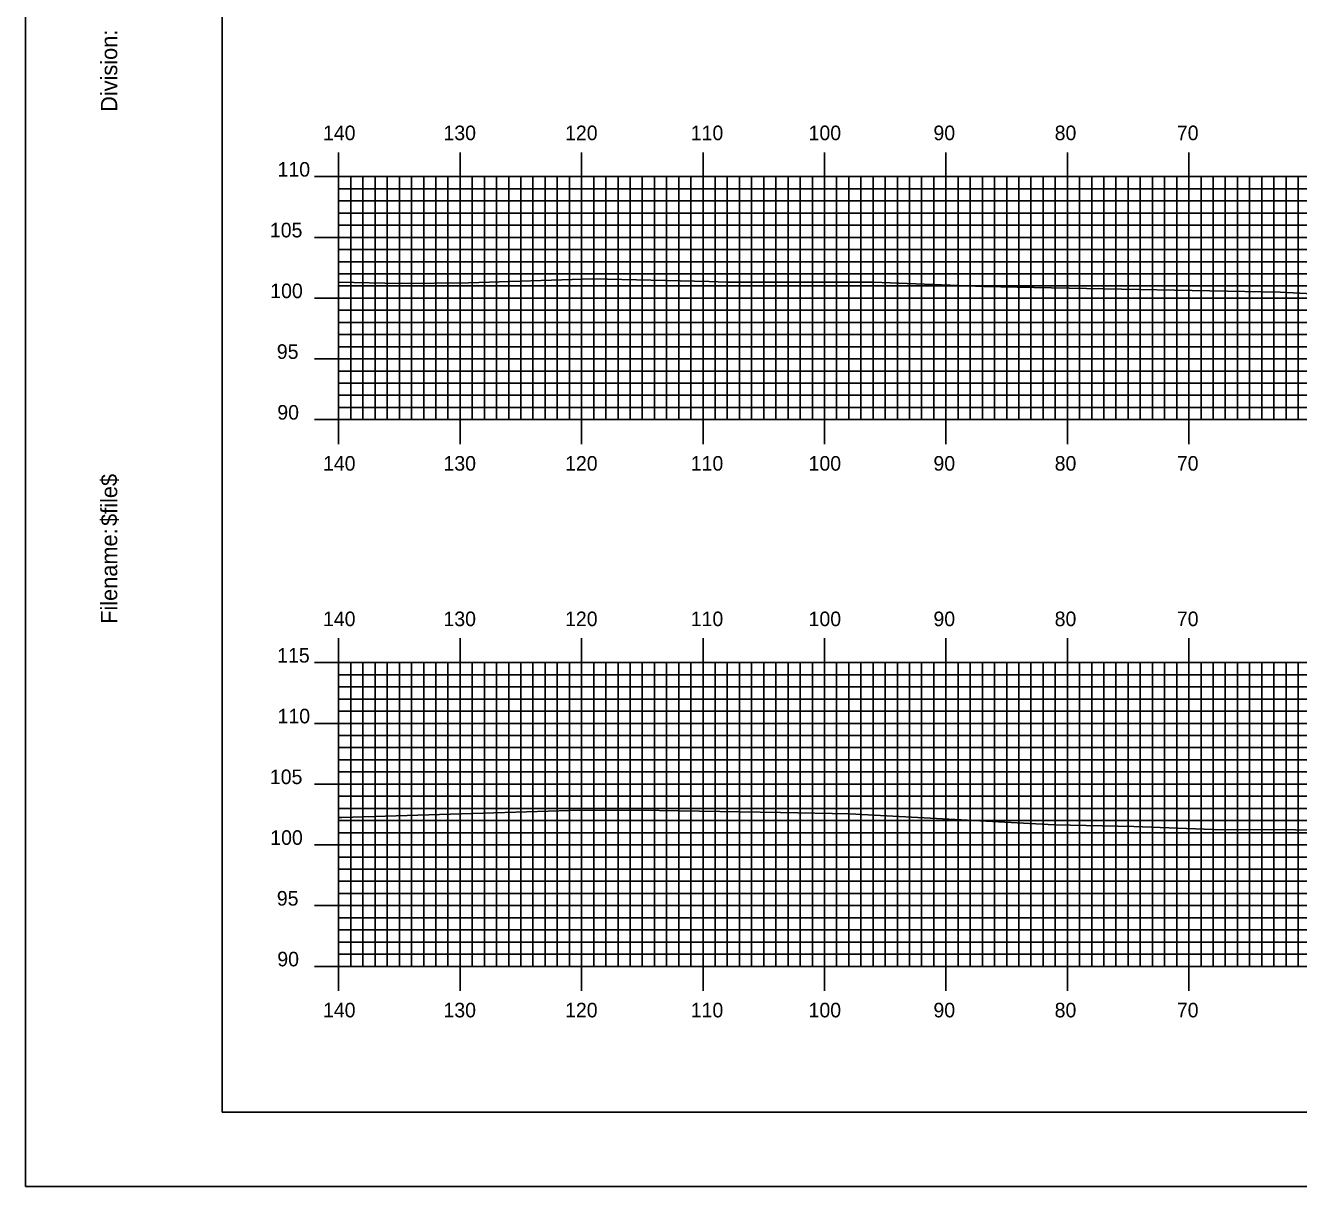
# Model space of a CAD drawing. Extents: x 1774383 to 1774727, y 442591 to 442811.
# Drawn here: x 1774383.4 to 1774488.2, y 442590.5 to 442686.1 of the extents above; entities that cross this region are included whole.
import ezdxf

# ---------------------------------------------------------------- set-up
doc = ezdxf.new("R2010")
doc.units = 0
for name, color, linetype in [('BORDER', 7, 'Continuous'), ('H_V ANNOTATION', 7, 'Continuous'), ('MAJOR', 7, 'Continuous'), ('MINOR', 7, 'Continuous'), ('PLOT BOUNDARY', 7, 'Continuous'), ('S_Roadway_Centerline', 7, 'Continuous')]:
    doc.layers.add(name, color=color, linetype=linetype)

msp = doc.modelspace()

# ---------------------------------------------------------------- linework, layer by layer
at = {"layer": 'BORDER'}
msp.add_lwpolyline([(1774399.57, 442596.67), (1774719.57, 442596.67), (1774719.57, 442806.67), (1774399.57, 442806.67)], close=True, dxfattribs=at)
at = {"layer": 'MAJOR'}
for p, q in [((1774409.17, 442675.67), (1774409.17, 442673.67)), ((1774419.17, 442675.67), (1774419.17, 442673.67)), ((1774429.17, 442675.67), (1774429.17, 442673.67)), ((1774439.17, 442675.67), (1774439.17, 442673.67)), ((1774449.17, 442675.67), (1774449.17, 442673.67)), ((1774459.17, 442675.67), (1774459.17, 442673.67)), ((1774469.17, 442675.67), (1774469.17, 442673.67)), ((1774479.17, 442675.67), (1774479.17, 442673.67)), ((1774407.17, 442673.67), (1774409.17, 442673.67)), ((1774409.17, 442673.67), (1774689.17, 442673.67)), ((1774409.17, 442653.67), (1774409.17, 442673.67)), ((1774409.17, 442653.67), (1774409.17, 442673.67)), ((1774409.17, 442673.67), (1774689.17, 442673.67)), ((1774419.17, 442653.67), (1774419.17, 442673.67)), ((1774429.17, 442653.67), (1774429.17, 442673.67)), ((1774439.17, 442653.67), (1774439.17, 442673.67)), ((1774449.17, 442653.67), (1774449.17, 442673.67)), ((1774459.17, 442653.67), (1774459.17, 442673.67)), ((1774469.17, 442653.67), (1774469.17, 442673.67)), ((1774479.17, 442653.67), (1774479.17, 442673.67)), ((1774407.17, 442668.67), (1774409.17, 442668.67)), ((1774409.17, 442668.67), (1774689.17, 442668.67)), ((1774407.17, 442663.67), (1774409.17, 442663.67)), ((1774409.17, 442663.67), (1774689.17, 442663.67)), ((1774407.17, 442658.67), (1774409.17, 442658.67)), ((1774409.17, 442658.67), (1774689.17, 442658.67)), ((1774407.17, 442653.67), (1774409.17, 442653.67)), ((1774409.17, 442653.67), (1774689.17, 442653.67)), ((1774409.17, 442653.67), (1774689.17, 442653.67)), ((1774409.17, 442651.66), (1774409.17, 442653.67)), ((1774419.17, 442651.66), (1774419.17, 442653.67)), ((1774429.17, 442651.66), (1774429.17, 442653.67)), ((1774439.17, 442651.66), (1774439.17, 442653.67)), ((1774449.17, 442651.66), (1774449.17, 442653.67)), ((1774459.17, 442651.66), (1774459.17, 442653.67)), ((1774469.17, 442651.66), (1774469.17, 442653.67)), ((1774479.17, 442651.66), (1774479.17, 442653.67)), ((1774409.17, 442635.67), (1774409.17, 442633.67)), ((1774419.17, 442635.67), (1774419.17, 442633.67)), ((1774429.17, 442635.67), (1774429.17, 442633.67)), ((1774439.17, 442635.67), (1774439.17, 442633.67)), ((1774449.17, 442635.67), (1774449.17, 442633.67)), ((1774459.17, 442635.67), (1774459.17, 442633.67)), ((1774469.17, 442635.67), (1774469.17, 442633.67)), ((1774479.17, 442635.67), (1774479.17, 442633.67)), ((1774407.17, 442633.67), (1774409.17, 442633.67)), ((1774409.17, 442633.67), (1774689.17, 442633.67)), ((1774409.17, 442608.67), (1774409.17, 442633.67)), ((1774409.17, 442608.67), (1774409.17, 442633.67)), ((1774409.17, 442633.67), (1774689.17, 442633.67)), ((1774419.17, 442608.67), (1774419.17, 442633.67)), ((1774429.17, 442608.67), (1774429.17, 442633.67)), ((1774439.17, 442608.67), (1774439.17, 442633.67)), ((1774449.17, 442608.67), (1774449.17, 442633.67)), ((1774459.17, 442608.67), (1774459.17, 442633.67)), ((1774469.17, 442608.67), (1774469.17, 442633.67)), ((1774479.17, 442608.67), (1774479.17, 442633.67)), ((1774407.17, 442628.67), (1774409.17, 442628.67)), ((1774409.17, 442628.67), (1774689.17, 442628.67)), ((1774407.17, 442623.67), (1774409.17, 442623.67)), ((1774409.17, 442623.67), (1774689.17, 442623.67)), ((1774407.17, 442618.67), (1774409.17, 442618.67)), ((1774409.17, 442618.67), (1774689.17, 442618.67)), ((1774407.17, 442613.67), (1774409.17, 442613.67)), ((1774409.17, 442613.67), (1774689.17, 442613.67)), ((1774407.17, 442608.67), (1774409.17, 442608.67)), ((1774409.17, 442608.67), (1774689.17, 442608.67)), ((1774409.17, 442608.67), (1774689.17, 442608.67)), ((1774409.17, 442606.66), (1774409.17, 442608.67)), ((1774419.17, 442606.66), (1774419.17, 442608.67)), ((1774429.17, 442606.66), (1774429.17, 442608.67)), ((1774439.17, 442606.66), (1774439.17, 442608.67)), ((1774449.17, 442606.66), (1774449.17, 442608.67)), ((1774459.17, 442606.66), (1774459.17, 442608.67)), ((1774469.17, 442606.66), (1774469.17, 442608.67)), ((1774479.17, 442606.66), (1774479.17, 442608.67))]:
    msp.add_line(p, q, dxfattribs=at)
at = {"layer": 'MINOR'}
for p, q in [((1774410.17, 442653.67), (1774410.17, 442673.67)), ((1774411.17, 442653.67), (1774411.17, 442673.67)), ((1774412.17, 442653.67), (1774412.17, 442673.67)), ((1774413.17, 442653.67), (1774413.17, 442673.67)), ((1774414.17, 442653.67), (1774414.17, 442673.67)), ((1774415.17, 442653.67), (1774415.17, 442673.67)), ((1774416.17, 442653.67), (1774416.17, 442673.67)), ((1774417.17, 442653.67), (1774417.17, 442673.67)), ((1774418.17, 442653.67), (1774418.17, 442673.67)), ((1774420.17, 442653.67), (1774420.17, 442673.67)), ((1774421.17, 442653.67), (1774421.17, 442673.67)), ((1774422.17, 442653.67), (1774422.17, 442673.67)), ((1774423.17, 442653.67), (1774423.17, 442673.67)), ((1774424.17, 442653.67), (1774424.17, 442673.67)), ((1774425.17, 442653.67), (1774425.17, 442673.67)), ((1774426.17, 442653.67), (1774426.17, 442673.67)), ((1774427.17, 442653.67), (1774427.17, 442673.67)), ((1774428.17, 442653.67), (1774428.17, 442673.67)), ((1774430.17, 442653.67), (1774430.17, 442673.67)), ((1774431.17, 442653.67), (1774431.17, 442673.67)), ((1774432.17, 442653.67), (1774432.17, 442673.67)), ((1774433.17, 442653.67), (1774433.17, 442673.67)), ((1774434.17, 442653.67), (1774434.17, 442673.67)), ((1774435.17, 442653.67), (1774435.17, 442673.67)), ((1774436.17, 442653.67), (1774436.17, 442673.67)), ((1774437.17, 442653.67), (1774437.17, 442673.67)), ((1774438.17, 442653.67), (1774438.17, 442673.67)), ((1774440.17, 442653.67), (1774440.17, 442673.67)), ((1774441.17, 442653.67), (1774441.17, 442673.67)), ((1774442.17, 442653.67), (1774442.17, 442673.67)), ((1774443.17, 442653.67), (1774443.17, 442673.67)), ((1774444.17, 442653.67), (1774444.17, 442673.67)), ((1774445.17, 442653.67), (1774445.17, 442673.67)), ((1774446.17, 442653.67), (1774446.17, 442673.67)), ((1774447.17, 442653.67), (1774447.17, 442673.67)), ((1774448.17, 442653.67), (1774448.17, 442673.67)), ((1774450.17, 442653.67), (1774450.17, 442673.67)), ((1774451.17, 442653.67), (1774451.17, 442673.67)), ((1774452.17, 442653.67), (1774452.17, 442673.67)), ((1774453.17, 442653.67), (1774453.17, 442673.67)), ((1774454.17, 442653.67), (1774454.17, 442673.67)), ((1774455.17, 442653.67), (1774455.17, 442673.67)), ((1774456.17, 442653.67), (1774456.17, 442673.67)), ((1774457.17, 442653.67), (1774457.17, 442673.67)), ((1774458.17, 442653.67), (1774458.17, 442673.67)), ((1774460.17, 442653.67), (1774460.17, 442673.67)), ((1774461.17, 442653.67), (1774461.17, 442673.67)), ((1774462.17, 442653.67), (1774462.17, 442673.67)), ((1774463.17, 442653.67), (1774463.17, 442673.67)), ((1774464.17, 442653.67), (1774464.17, 442673.67)), ((1774465.17, 442653.67), (1774465.17, 442673.67)), ((1774466.17, 442653.67), (1774466.17, 442673.67)), ((1774467.17, 442653.67), (1774467.17, 442673.67)), ((1774468.17, 442653.67), (1774468.17, 442673.67)), ((1774470.17, 442653.67), (1774470.17, 442673.67)), ((1774471.17, 442653.67), (1774471.17, 442673.67)), ((1774472.17, 442653.67), (1774472.17, 442673.67)), ((1774473.17, 442653.67), (1774473.17, 442673.67)), ((1774474.17, 442653.67), (1774474.17, 442673.67)), ((1774475.17, 442653.67), (1774475.17, 442673.67)), ((1774476.17, 442653.67), (1774476.17, 442673.67)), ((1774477.17, 442653.67), (1774477.17, 442673.67)), ((1774478.17, 442653.67), (1774478.17, 442673.67)), ((1774480.17, 442653.67), (1774480.17, 442673.67)), ((1774481.17, 442653.67), (1774481.17, 442673.67)), ((1774482.17, 442653.67), (1774482.17, 442673.67)), ((1774483.17, 442653.67), (1774483.17, 442673.67)), ((1774484.17, 442653.67), (1774484.17, 442673.67)), ((1774485.17, 442653.67), (1774485.17, 442673.67)), ((1774486.17, 442653.67), (1774486.17, 442673.67)), ((1774487.17, 442653.67), (1774487.17, 442673.67)), ((1774488.17, 442653.67), (1774488.17, 442673.67)), ((1774409.17, 442672.67), (1774689.17, 442672.67)), ((1774409.17, 442672.67), (1774411.18, 442672.67)), ((1774409.17, 442671.67), (1774689.17, 442671.67)), ((1774409.17, 442671.67), (1774411.18, 442671.67)), ((1774409.17, 442670.67), (1774689.17, 442670.67)), ((1774409.17, 442670.67), (1774411.18, 442670.67)), ((1774409.17, 442669.67), (1774689.17, 442669.67)), ((1774409.17, 442669.67), (1774411.18, 442669.67)), ((1774409.17, 442667.67), (1774689.17, 442667.67)), ((1774409.17, 442667.67), (1774411.18, 442667.67)), ((1774409.17, 442666.67), (1774689.17, 442666.67)), ((1774409.17, 442666.67), (1774411.18, 442666.67)), ((1774409.17, 442665.67), (1774689.17, 442665.67)), ((1774409.17, 442665.67), (1774411.18, 442665.67)), ((1774409.17, 442664.67), (1774689.17, 442664.67)), ((1774409.17, 442664.67), (1774411.18, 442664.67)), ((1774409.17, 442662.67), (1774689.17, 442662.67)), ((1774409.17, 442662.67), (1774411.18, 442662.67)), ((1774409.17, 442661.67), (1774689.17, 442661.67)), ((1774409.17, 442661.67), (1774411.18, 442661.67)), ((1774409.17, 442660.67), (1774689.17, 442660.67)), ((1774409.17, 442660.67), (1774411.18, 442660.67)), ((1774409.17, 442659.67), (1774689.17, 442659.67)), ((1774409.17, 442659.67), (1774411.18, 442659.67)), ((1774409.17, 442657.67), (1774689.17, 442657.67)), ((1774409.17, 442657.67), (1774411.18, 442657.67)), ((1774409.17, 442656.67), (1774689.17, 442656.67)), ((1774409.17, 442656.67), (1774411.18, 442656.67)), ((1774409.17, 442655.67), (1774689.17, 442655.67)), ((1774409.17, 442655.67), (1774411.18, 442655.67)), ((1774409.17, 442654.67), (1774689.17, 442654.67)), ((1774409.17, 442654.67), (1774411.18, 442654.67)), ((1774410.17, 442608.67), (1774410.17, 442633.67)), ((1774411.17, 442608.67), (1774411.17, 442633.67)), ((1774412.17, 442608.67), (1774412.17, 442633.67)), ((1774413.17, 442608.67), (1774413.17, 442633.67)), ((1774414.17, 442608.67), (1774414.17, 442633.67)), ((1774415.17, 442608.67), (1774415.17, 442633.67)), ((1774416.17, 442608.67), (1774416.17, 442633.67)), ((1774417.17, 442608.67), (1774417.17, 442633.67)), ((1774418.17, 442608.67), (1774418.17, 442633.67)), ((1774420.17, 442608.67), (1774420.17, 442633.67)), ((1774421.17, 442608.67), (1774421.17, 442633.67)), ((1774422.17, 442608.67), (1774422.17, 442633.67)), ((1774423.17, 442608.67), (1774423.17, 442633.67)), ((1774424.17, 442608.67), (1774424.17, 442633.67)), ((1774425.17, 442608.67), (1774425.17, 442633.67)), ((1774426.17, 442608.67), (1774426.17, 442633.67)), ((1774427.17, 442608.67), (1774427.17, 442633.67)), ((1774428.17, 442608.67), (1774428.17, 442633.67)), ((1774430.17, 442608.67), (1774430.17, 442633.67)), ((1774431.17, 442608.67), (1774431.17, 442633.67)), ((1774432.17, 442608.67), (1774432.17, 442633.67)), ((1774433.17, 442608.67), (1774433.17, 442633.67)), ((1774434.17, 442608.67), (1774434.17, 442633.67)), ((1774435.17, 442608.67), (1774435.17, 442633.67)), ((1774436.17, 442608.67), (1774436.17, 442633.67)), ((1774437.17, 442608.67), (1774437.17, 442633.67)), ((1774438.17, 442608.67), (1774438.17, 442633.67)), ((1774440.17, 442608.67), (1774440.17, 442633.67)), ((1774441.17, 442608.67), (1774441.17, 442633.67)), ((1774442.17, 442608.67), (1774442.17, 442633.67)), ((1774443.17, 442608.67), (1774443.17, 442633.67)), ((1774444.17, 442608.67), (1774444.17, 442633.67)), ((1774445.17, 442608.67), (1774445.17, 442633.67)), ((1774446.17, 442608.67), (1774446.17, 442633.67)), ((1774447.17, 442608.67), (1774447.17, 442633.67)), ((1774448.17, 442608.67), (1774448.17, 442633.67)), ((1774450.17, 442608.67), (1774450.17, 442633.67)), ((1774451.17, 442608.67), (1774451.17, 442633.67)), ((1774452.17, 442608.67), (1774452.17, 442633.67)), ((1774453.17, 442608.67), (1774453.17, 442633.67)), ((1774454.17, 442608.67), (1774454.17, 442633.67)), ((1774455.17, 442608.67), (1774455.17, 442633.67)), ((1774456.17, 442608.67), (1774456.17, 442633.67)), ((1774457.17, 442608.67), (1774457.17, 442633.67)), ((1774458.17, 442608.67), (1774458.17, 442633.67)), ((1774460.17, 442608.67), (1774460.17, 442633.67)), ((1774461.17, 442608.67), (1774461.17, 442633.67)), ((1774462.17, 442608.67), (1774462.17, 442633.67)), ((1774463.17, 442608.67), (1774463.17, 442633.67)), ((1774464.17, 442608.67), (1774464.17, 442633.67)), ((1774465.17, 442608.67), (1774465.17, 442633.67)), ((1774466.17, 442608.67), (1774466.17, 442633.67)), ((1774467.17, 442608.67), (1774467.17, 442633.67)), ((1774468.17, 442608.67), (1774468.17, 442633.67)), ((1774470.17, 442608.67), (1774470.17, 442633.67)), ((1774471.17, 442608.67), (1774471.17, 442633.67)), ((1774472.17, 442608.67), (1774472.17, 442633.67)), ((1774473.17, 442608.67), (1774473.17, 442633.67)), ((1774474.17, 442608.67), (1774474.17, 442633.67)), ((1774475.17, 442608.67), (1774475.17, 442633.67)), ((1774476.17, 442608.67), (1774476.17, 442633.67)), ((1774477.17, 442608.67), (1774477.17, 442633.67)), ((1774478.17, 442608.67), (1774478.17, 442633.67)), ((1774480.17, 442608.67), (1774480.17, 442633.67)), ((1774481.17, 442608.67), (1774481.17, 442633.67)), ((1774482.17, 442608.67), (1774482.17, 442633.67)), ((1774483.17, 442608.67), (1774483.17, 442633.67)), ((1774484.17, 442608.67), (1774484.17, 442633.67)), ((1774485.17, 442608.67), (1774485.17, 442633.67)), ((1774486.17, 442608.67), (1774486.17, 442633.67)), ((1774487.17, 442608.67), (1774487.17, 442633.67)), ((1774488.17, 442608.67), (1774488.17, 442633.67)), ((1774409.17, 442632.67), (1774689.17, 442632.67)), ((1774409.17, 442632.67), (1774411.18, 442632.67)), ((1774409.17, 442631.67), (1774689.17, 442631.67)), ((1774409.17, 442631.67), (1774411.18, 442631.67)), ((1774409.17, 442630.67), (1774689.17, 442630.67)), ((1774409.17, 442630.67), (1774411.18, 442630.67)), ((1774409.17, 442629.67), (1774689.17, 442629.67)), ((1774409.17, 442629.67), (1774411.18, 442629.67)), ((1774409.17, 442627.67), (1774689.17, 442627.67)), ((1774409.17, 442627.67), (1774411.18, 442627.67)), ((1774409.17, 442626.67), (1774689.17, 442626.67)), ((1774409.17, 442626.67), (1774411.18, 442626.67)), ((1774409.17, 442625.67), (1774689.17, 442625.67)), ((1774409.17, 442625.67), (1774411.18, 442625.67)), ((1774409.17, 442624.67), (1774689.17, 442624.67)), ((1774409.17, 442624.67), (1774411.18, 442624.67)), ((1774409.17, 442622.67), (1774689.17, 442622.67)), ((1774409.17, 442622.67), (1774411.18, 442622.67)), ((1774409.17, 442621.67), (1774689.17, 442621.67)), ((1774409.17, 442621.67), (1774411.18, 442621.67)), ((1774409.17, 442620.67), (1774689.17, 442620.67)), ((1774409.17, 442620.67), (1774411.18, 442620.67)), ((1774409.17, 442619.67), (1774689.17, 442619.67)), ((1774409.17, 442619.67), (1774411.18, 442619.67)), ((1774409.17, 442617.67), (1774689.17, 442617.67)), ((1774409.17, 442617.67), (1774411.18, 442617.67)), ((1774409.17, 442616.67), (1774689.17, 442616.67)), ((1774409.17, 442616.67), (1774411.18, 442616.67)), ((1774409.17, 442615.67), (1774689.17, 442615.67)), ((1774409.17, 442615.67), (1774411.18, 442615.67)), ((1774409.17, 442614.67), (1774689.17, 442614.67)), ((1774409.17, 442614.67), (1774411.18, 442614.67)), ((1774409.17, 442612.67), (1774689.17, 442612.67)), ((1774409.17, 442612.67), (1774411.18, 442612.67)), ((1774409.17, 442611.67), (1774689.17, 442611.67)), ((1774409.17, 442611.67), (1774411.18, 442611.67)), ((1774409.17, 442610.67), (1774689.17, 442610.67)), ((1774409.17, 442610.67), (1774411.18, 442610.67)), ((1774409.17, 442609.67), (1774689.17, 442609.67)), ((1774409.17, 442609.67), (1774411.18, 442609.67))]:
    msp.add_line(p, q, dxfattribs=at)
at = {"layer": 'PLOT BOUNDARY'}
msp.add_lwpolyline([(1774383.39, 442590.55), (1774723.39, 442590.55), (1774723.39, 442810.55), (1774383.39, 442810.55)], close=True, dxfattribs=at)
at = {"layer": 'S_Roadway_Centerline'}
for points in [[(1774409.17, 442664.98), (1774414.23, 442664.87), (1774419.86, 442664.94), (1774430.1, 442665.25), (1774439.68, 442665.04), (1774441.17, 442664.99), (1774442.85, 442664.98), (1774453.19, 442664.99), (1774462.31, 442664.63), (1774466.4, 442664.54), (1774486.7, 442664.16), (1774489.38, 442664.03)], [(1774409.17, 442620.91), (1774409.42, 442620.92), (1774422.84, 442621.32), (1774428.2, 442621.5), (1774433.88, 442621.53), (1774445.56, 442621.32), (1774451.22, 442621.21), (1774468.1, 442620.33), (1774474.64, 442620.19), (1774481.88, 442619.91), (1774486.89, 442619.93), (1774491.13, 442619.82), (1774505.75, 442619.32), (1774509.5, 442619.03), (1774513.06, 442619.09), (1774530.18, 442618.9), (1774535.38, 442618.79), (1774552.35, 442618.76), (1774555.24, 442618.73), (1774558.14, 442618.67), (1774568.02, 442618.45), (1774575.9, 442618.39), (1774578.72, 442618.36), (1774600.44, 442617.87)]]:
    msp.add_lwpolyline(points, dxfattribs=at)

# ---------------------------------------------------------------- texts
at = {"layer": 'BORDER'}
for s, p in [('Division:', (1774390.94, 442679)), ('$file$', (1774390.94, 442644.92)), ('Filename:', (1774390.94, 442636.86))]:
    msp.add_text(s, height=1.339, rotation=90, dxfattribs=at).set_placement(p)
at = {"layer": 'H_V ANNOTATION'}
for s, p in [('140', (1774407.88, 442676.67)), ('130', (1774417.8, 442676.67)), ('120', (1774427.81, 442676.67)), ('110', (1774438.16, 442676.67)), ('100', (1774447.86, 442676.67)), ('90', (1774458.14, 442676.67)), ('80', (1774468.12, 442676.67)), ('70', (1774478.18, 442676.67)), ('110', (1774404.14, 442673.67)), ('105', (1774403.51, 442668.67)), ('100', (1774403.54, 442663.67)), ('95', (1774404.08, 442658.67)), ('90', (1774404.12, 442653.67)), ('140', (1774407.88, 442649.47)), ('130', (1774417.8, 442649.47)), ('120', (1774427.81, 442649.47)), ('110', (1774438.16, 442649.47)), ('100', (1774447.86, 442649.47)), ('90', (1774458.14, 442649.47)), ('80', (1774468.12, 442649.47)), ('70', (1774478.18, 442649.47)), ('140', (1774407.88, 442636.67)), ('130', (1774417.8, 442636.67)), ('120', (1774427.81, 442636.67)), ('110', (1774438.16, 442636.67)), ('100', (1774447.86, 442636.67)), ('90', (1774458.14, 442636.67)), ('80', (1774468.12, 442636.67)), ('70', (1774478.18, 442636.67)), ('115', (1774404.11, 442633.67)), ('110', (1774404.14, 442628.67)), ('105', (1774403.51, 442623.67)), ('100', (1774403.54, 442618.67)), ('95', (1774404.08, 442613.67)), ('90', (1774404.12, 442608.67)), ('140', (1774407.88, 442604.47)), ('130', (1774417.8, 442604.47)), ('120', (1774427.81, 442604.47)), ('110', (1774438.16, 442604.47)), ('100', (1774447.86, 442604.47)), ('90', (1774458.14, 442604.47)), ('80', (1774468.12, 442604.47)), ('70', (1774478.18, 442604.47))]:
    msp.add_text(s, height=1.2, dxfattribs=at).set_placement(p)
at = {"layer": 'MAJOR'}
for p in [(1774409.16, 442653.67), (1774409.16, 442608.67)]:
    msp.add_text('-', height=0.012, dxfattribs=at).set_placement(p)

doc.saveas('drawing.dxf')
